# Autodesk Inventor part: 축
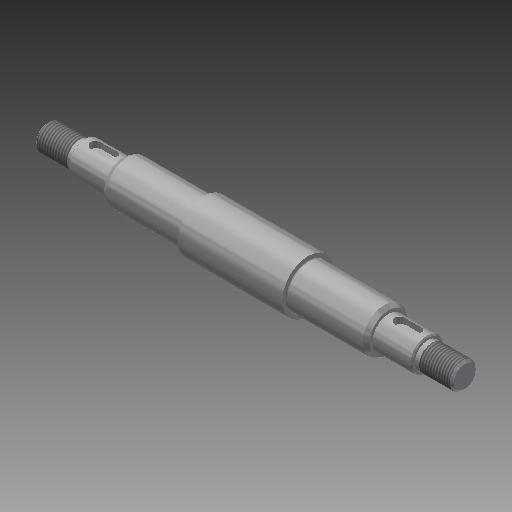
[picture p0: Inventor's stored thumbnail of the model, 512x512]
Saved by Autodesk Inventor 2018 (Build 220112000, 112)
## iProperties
Created: 2018-11
Part Number: 축
Material: 강철, 연강
Document SubType Name: Modeling
Designer: mduedu
Density: 1 g/cm^3
Appearance: 강철
Author: mduedu
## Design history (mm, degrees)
sketch "스케치1"
  geometry: L1 (-24, 0)-(24, 0); L2 (24, 0)-(24, 12); L3 (24, 12)-(-24, 12); L4 (-24, 12)-(-24, 0); L5 (-24, 0)-(-79, 0); L6 (-79, 0)-(-79, 7.5); L7 (-79, 7.5)-(-61, 7.5); L8 (-24, 7.5)-(-24, 0); L9 (-79, 0)-(-96, 0); L10 (-96, 0)-(-96, 6); L11 (-96, 6)-(-79, 6); L12 (-79, 6)-(-79, 0); L13 (0, 0)-(0, 12); L14 (24, 0)-(79, 0); L15 (79, 0)-(79, 7.5); L16 (79, 7.5)-(61, 7.5); L17 (24, 7.5)-(24, 0); L18 (79, 0)-(96, 0); L19 (96, 0)-(96, 6); L20 (96, 6)-(79, 6); L21 (79, 6)-(79, 0); L22 (-61, 7.5)-(-61, 8.85); L23 (-59.008, 10)-(-24, 10); L24 (24, 10)-(59.008, 10); L25 (61, 8.85)-(61, 7.5); L26 (-61, 8.85)-(-59.008, 10); L27 (61, 8.85)-(59.008, 10); 1 further point
  constraints: 54 end point, 9 parallel, 6 symmetric about line, 4 horizontal, 4 perpendicular, 2 midpoint, 2 point on line, 1 coincident
  dimensions: "d0" = 24 diameter of L3 L1; "d2" = 15 diameter of L7 L5; "d3" = 12 diameter of L11 L9; "d4" = 48 distance of L2.end L3.end; "d5" = 55 distance of L6.end L8.start; "d6" = 192 distance between parallel lines of L19 L10; "d24" = 20 diameter of L23 L5; "d25" = 18 distance of L6.end L7.end; "d26" = 18 distance of L15.end L16.end; "d27" = 20 diameter of L24 L14; "d28" = 55 distance between parallel lines of L15 L2; "d29" = 30 deg angle of L23 L26; "d30" = 17.7 diameter of L22.end L5; "d31" = 30 deg angle of L24 L27; "d32" = 17.7 diameter of L25.start L14
revolve "회전1" sketch "스케치1" stored, may be unused: angle "d7" = 90 deg
fillet "모깎기1" dims "d8" = 0.6
node "작업 평면1"
sketch "스케치2" dims "d11" = 12
  geometry: L1 (-3.5, 2.5)-(3.5, 2.5); L2 (3.5, 2.5)-(3.5, -2.5); L3 (3.5, -2.5)-(-3.5, -2.5); L4 (-3.5, -2.5)-(-3.5, 2.5); L5 (9, 7.5)-(9, -7.5) reference; 3 further points
  constraints: 8 end point, 2 midpoint, 2 parallel, 2 vertical alignment, 1 horizontal, 1 horizontal alignment, 1 perpendicular, 4 other
  dimensions: "d9" = 3 dimension on L5; "d10" = 5 distance between parallel lines of L3 L1
extrude "돌출1" cut sketch "스케치2" distance "d12" = 3; taper "d13" = 0 deg
chamfer "모따기1" distance "d14" = 0.5; stored, may be unused: second distance "d15" = 2, angle "d16" = 45 deg
feature "스레드1" dims "d17" = 15, "d18" = 0
feature "스레드2" dims "d19" = 15, "d20" = 0
chamfer "모따기2" distance "d21" = 1; stored, may be unused: second distance "d22" = 2, angle "d23" = 45 deg
node "솔리드1"
mirror "대칭1"
